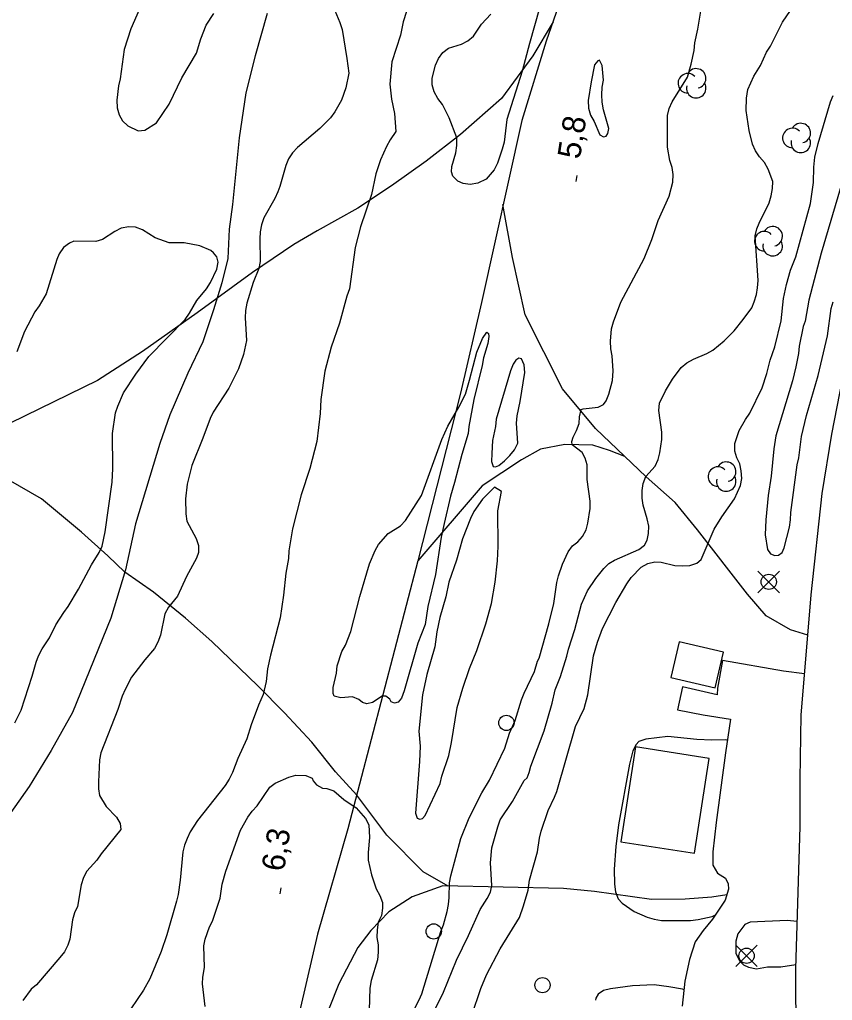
# Model space of a CAD drawing. Extents: x 282461 to 284471, y 5554090 to 5557646.
# Drawn here: x 282958.2 to 283064.7, y 5555423.2 to 5555551.7 of the extents above; entities that cross this region are included whole.
import ezdxf

# ---------------------------------------------------------------- set-up
doc = ezdxf.new("R2010")
doc.units = 0
for name, color, linetype in [('Niveau 1', 7, 'Continuous'), ('Niveau 19', 7, 'Continuous'), ('Niveau 2', 7, 'Continuous'), ('Niveau 21', 7, 'Continuous'), ('Niveau 22', 7, 'Continuous'), ('Niveau 3', 7, 'Continuous'), ('Niveau 31', 7, 'Continuous'), ('Niveau 36', 7, 'Continuous'), ('Niveau 44', 7, 'Continuous')]:
    doc.layers.add(name, color=color, linetype=linetype)

msp = doc.modelspace()

# ---------------------------------------------------------------- linework, layer by layer
at = {"layer": 'Niveau 1'}
for points in [[(283009.79, 5555555.65), (283008.45, 5555551.38), (283008.07, 5555549.65), (283006.95, 5555546.18), (283006.69, 5555543.24), (283006.88, 5555541.28), (283007.31, 5555539.38), (283007.45, 5555537.04)], [(283036.95, 5555514.69), (283040.01, 5555520.4), (283041.02, 5555522.9), (283041.85, 5555525.4), (283043.26, 5555528.55), (283043.76, 5555530.4), (283043.81, 5555531.39), (283043.68, 5555532.32), (283043.38, 5555533.24), (283043.07, 5555534.97), (283043.05, 5555539.11), (283043.28, 5555540.03), (283043.67, 5555540.9), (283045.66, 5555544.14), (283046.16, 5555545.87), (283046.55, 5555547.66), (283046.65, 5555548.64), (283047.04, 5555550.43), (283047.53, 5555553.31)], [(283007.45, 5555537.04), (283006.72, 5555535.93), (283006.26, 5555535.06), (283005.47, 5555533.31), (283004.86, 5555531.51), (283004.26, 5555528.78), (283002.86, 5555524.53), (283002.14, 5555521.86), (283001.4, 5555516.41), (283001.06, 5555515.48), (283000.07, 5555511.94), (282999.01, 5555508.8), (282998.18, 5555505.66), (282997.64, 5555501.95), (282997.55, 5555500.1), (282997.13, 5555496.44), (282996.19, 5555492.9), (282995.08, 5555489.47), (282993.92, 5555485), (282993.43, 5555482.1), (282993.39, 5555481.11), (282993.06, 5555479.2), (282992.75, 5555476.3), (282992.32, 5555473.34), (282991.05, 5555468.47), (282990.67, 5555466.67), (282990.46, 5555464.99), (282990.08, 5555463.3), (282989.46, 5555461.91), (282988.5, 5555459.35), (282987.95, 5555457.49), (282986.77, 5555454.93), (282986.09, 5555453.07), (282985.64, 5555452.2), (282985.13, 5555451.38), (282981.49, 5555446.82), (282980.52, 5555445.31), (282980.13, 5555444.43), (282979.79, 5555443.56), (282979.57, 5555442.69), (282979.21, 5555438.98), (282978.94, 5555437.13), (282978.72, 5555436.26), (282977.45, 5555431.84), (282976.72, 5555429.63), (282975.26, 5555426.09), (282974.41, 5555424.57), (282972.77, 5555422.12)], [(283009.22, 5555420.74), (283010.52, 5555423.3), (283010.86, 5555424.12), (283013.36, 5555432.25), (283013.7, 5555433.12), (283014.2, 5555434.87), (283014.36, 5555435.79), (283014.47, 5555436.72), (283014.5, 5555438.63), (283014.66, 5555439.56), (283015.99, 5555444.44), (283017.06, 5555447.17), (283018.75, 5555450.43), (283019.72, 5555452.07), (283021.75, 5555456.26), (283022.36, 5555458.23), (283023.09, 5555459.92), (283023.93, 5555462.59), (283024.27, 5555463.47), (283025.62, 5555466.32), (283026.01, 5555467.66), (283026.23, 5555468.06), (283027.51, 5555472.54), (283028.17, 5555475.21), (283028.54, 5555477.99), (283028.76, 5555478.86), (283029.32, 5555480.38), (283030.06, 5555482.01), (283030.63, 5555482.76), (283031.31, 5555483.29), (283031.94, 5555484), (283032.39, 5555484.87), (283032.62, 5555485.74), (283032.94, 5555487.66), (283032.93, 5555488.64), (283032.55, 5555491.47), (283032.52, 5555493.38), (283032.28, 5555494.25), (283031.87, 5555495), (283030.58, 5555496.02), (283030.52, 5555496.43), (283030.68, 5555497.01), (283031.14, 5555497.88), (283031.47, 5555498.81), (283031.52, 5555499.68), (283031.74, 5555500.61), (283032.03, 5555500.73), (283033.99, 5555500.93), (283034.68, 5555501.28), (283035.02, 5555501.75), (283035.36, 5555502.62), (283035.86, 5555504.42), (283035.96, 5555505.7), (283035.82, 5555507.67), (283035.64, 5555508.59), (283035.57, 5555509.58), (283035.72, 5555511.2), (283036, 5555512.13), (283036.95, 5555514.69)]]:
    msp.add_lwpolyline(points, dxfattribs=at)
at = {"layer": 'Niveau 19'}
for points in [[(283061.02, 5555466), (283058.27, 5555466.34), (283050.25, 5555467.76), (283049.6, 5555464.15), (283049.55, 5555463.28), (283045.02, 5555464.33), (283044.36, 5555461.31), (283047.73, 5555460.65), (283051.33, 5555460.06), (283050.64, 5555455.68), (283049.42, 5555446.55), (283049, 5555442.72), (283049.01, 5555440.97), (283049.59, 5555439.92), (283050.66, 5555439.27), (283051.02, 5555438.52), (283051.03, 5555437.82), (283050.63, 5555436.36), (283048.97, 5555433.9), (283047.72, 5555432.38), (283046.69, 5555430.92), (283045.92, 5555428.6), (283045.34, 5555425.77), (283044.99, 5555422.47)], [(283060.06, 5555433.58), (283058.74, 5555433.7), (283053.88, 5555433.47), (283053.18, 5555433.17), (283052.27, 5555431.94), (283051.99, 5555431.01), (283052.01, 5555429.44), (283052.49, 5555428.41), (283053.02, 5555427.89), (283053.66, 5555427.61), (283054.7, 5555427.39), (283056.15, 5555427.63), (283057.89, 5555427.65), (283059.88, 5555427.95)]]:
    msp.add_lwpolyline(points, dxfattribs=at)
at = {"layer": 'Niveau 2'}
for points in [[(283048.2, 5555507.95), (283049, 5555508.42), (283050.5, 5555509.6), (283051.81, 5555510.94), (283052.95, 5555512.41), (283054.09, 5555513.93), (283054.43, 5555514.74), (283054.71, 5555515.67), (283054.87, 5555516.54), (283054.92, 5555517.53), (283054.56, 5555523.38), (283054.78, 5555524.31), (283055.06, 5555525.01), (283056.36, 5555527.69), (283056.64, 5555528.62), (283056.8, 5555529.55), (283056.84, 5555530.48), (283056.25, 5555532.09), (283055.77, 5555532.96), (283055.13, 5555533.7), (283054.59, 5555534.51), (283054.18, 5555535.37), (283053.75, 5555537.17), (283053.37, 5555539.77), (283053.41, 5555541.39), (283053.57, 5555542.55), (283054.37, 5555544.28), (283055.23, 5555545.67), (283056.02, 5555547.41), (283056.53, 5555548.22), (283058.12, 5555551.35), (283060.79, 5555555.29)], [(282999.02, 5555553.94), (283000.15, 5555551.3), (283000.45, 5555550.38), (283001.06, 5555546.58), (283001.31, 5555544.68), (283000.93, 5555542.77), (283000.37, 5555541.15), (282999.46, 5555539.59), (282998.89, 5555538.83), (282997.52, 5555537.44), (282994.6, 5555534.94), (282993.91, 5555534.25), (282993.4, 5555533.44), (282993.06, 5555532.57), (282992.28, 5555529.83), (282992, 5555529.13), (282991.6, 5555528.26), (282990.19, 5555525.75), (282989.85, 5555524.82), (282989.69, 5555523.89), (282989.64, 5555522.96), (282989.68, 5555520), (282989.51, 5555519.08), (282988.78, 5555517.27), (282987.95, 5555514.54), (282987.79, 5555513.61), (282987.74, 5555512.62), (282987.89, 5555509.67), (282987.51, 5555507.81), (282986.84, 5555505.95), (282985.6, 5555503.44), (282983.55, 5555500.29), (282983.16, 5555499.47), (282982.2, 5555496.86), (282980.74, 5555493.3), (282980.13, 5555490.86), (282979.93, 5555488.95), (282979.95, 5555486.98), (282980.08, 5555486), (282981.32, 5555483.75), (282981.62, 5555482.83), (282981.63, 5555481.9), (282981.35, 5555481.14), (282980.05, 5555478.75), (282978.87, 5555476.19), (282977.67, 5555474.73), (282977.22, 5555473.85), (282976.62, 5555471.07), (282976.28, 5555470.14), (282975.83, 5555469.32), (282974.57, 5555467.86), (282972.86, 5555465.58), (282972.01, 5555463.95), (282971.62, 5555463.07), (282971.06, 5555461.33)], [(282973.84, 5555552.97), (282972.77, 5555550.48), (282971.87, 5555547.76), (282971.34, 5555543.95), (282971.12, 5555543.03), (282970.9, 5555541.13), (282970.97, 5555540.15), (282971.21, 5555539.22), (282971.68, 5555538.42), (282972.38, 5555537.79), (282973.72, 5555537.11), (282974.58, 5555537.23), (282976.13, 5555538.16), (282977.78, 5555540.6), (282979.42, 5555544.07), (282981.35, 5555547.31), (282981.91, 5555549.16), (282982.64, 5555550.95), (282983.61, 5555552.51)], [(283018.23, 5555530.28), (283017.2, 5555530.1), (283016.27, 5555530.21), (283015.58, 5555530.55), (283014.94, 5555531.18), (283014.76, 5555531.75), (283014.81, 5555532.44), (283015.31, 5555534.23), (283015.47, 5555535.21), (283015.46, 5555536.19), (283014.45, 5555538.83), (283013.57, 5555540.55), (283012.98, 5555541.35), (283012.51, 5555542.22), (283012.22, 5555543.13), (283012.21, 5555544), (283012.65, 5555545.73), (283013.05, 5555546.59), (283013.61, 5555547.4), (283014.36, 5555547.93), (283016.08, 5555548.46), (283016.89, 5555548.92), (283017.63, 5555549.5), (283018.71, 5555551.07), (283019.91, 5555552.4)], [(283026.31, 5555553.19), (283024.97, 5555548.58), (283024.03, 5555544.94), (283022.01, 5555538.59), (283021.64, 5555535.66), (283021.42, 5555534.73), (283020.8, 5555532.89), (283020.35, 5555532.02), (283019.32, 5555530.8), (283018.23, 5555530.28)], [(283033.04, 5555543.56), (283032.66, 5555541.08), (283032.73, 5555540.11), (283032.97, 5555539.19), (283033.44, 5555538.33), (283034.21, 5555536.6), (283034.67, 5555536.32), (283035.02, 5555536.44), (283035.25, 5555536.78), (283035.36, 5555537.42), (283034.69, 5555539.89), (283034.51, 5555540.87), (283034.44, 5555541.85), (283034.49, 5555542.82), (283034.66, 5555543.75), (283034.52, 5555545.7), (283034.17, 5555546.39), (283033.94, 5555546.28), (283033.48, 5555545.75), (283033.04, 5555543.56)], [(283017.43, 5555421.31), (283018.61, 5555424.8), (283019.34, 5555426.61), (283021.15, 5555429.99), (283023.65, 5555434.08), (283024.21, 5555435.65), (283024.82, 5555437.69), (283024.98, 5555438.97), (283026.04, 5555442.69), (283026.3, 5555444.49), (283026.52, 5555445.42), (283027.42, 5555448.1), (283028.27, 5555449.85), (283028.55, 5555450.61), (283030.99, 5555459.1), (283032.12, 5555461.49), (283032.62, 5555463.24), (283033.37, 5555468.35), (283033.87, 5555470.15), (283034.55, 5555471.96), (283036.3, 5555475.34), (283037.72, 5555477.8), (283038.29, 5555478.61), (283039.61, 5555479.96), (283040.47, 5555480.44), (283041.4, 5555480.68), (283042.21, 5555480.63), (283044.01, 5555480.19), (283045, 5555480.14), (283045.98, 5555480.21), (283046.9, 5555480.51), (283047.48, 5555480.98), (283049.17, 5555484.95), (283050.19, 5555486.58), (283051.85, 5555488.92), (283052.64, 5555490.67), (283052.8, 5555491.6), (283052.73, 5555492.59), (283052.54, 5555493.51), (283052.13, 5555494.32), (283051.89, 5555495.19), (283051.87, 5555496.17), (283052.43, 5555497.86), (283053.28, 5555499.32), (283053.85, 5555500.14), (283055.44, 5555503.47), (283056.05, 5555505.33), (283056.49, 5555507.07), (283057.11, 5555508.82), (283057.94, 5555512.25), (283058.25, 5555515.16), (283058.63, 5555517.02), (283059.19, 5555518.88), (283059.87, 5555520.63), (283061.81, 5555527.61), (283062.18, 5555530.34), (283062.22, 5555532.38), (283062.34, 5555533.69), (283062.79, 5555535.48), (283064.41, 5555540.92), (283064.75, 5555541.73)], [(283066.85, 5555533.51), (283063.17, 5555521.1), (283061.57, 5555514.93), (283061.08, 5555512.19), (283060.85, 5555511.5), (283060.3, 5555508.93), (283060.2, 5555507.95), (283059.87, 5555506.2), (283059.43, 5555504.4), (283057.26, 5555497.17), (283056.99, 5555495.49), (283056.62, 5555491.88), (283056.25, 5555489.38)], [(282981.78, 5555522.06), (282979.75, 5555522.44), (282977.78, 5555522.47), (282975.92, 5555523.09), (282974.28, 5555524.17), (282973.35, 5555524.51), (282972.49, 5555524.55), (282971.5, 5555524.37), (282970.64, 5555523.95), (282969.03, 5555522.89), (282968.17, 5555522.65), (282965.27, 5555522.67), (282964.7, 5555522.43), (282963.95, 5555521.84), (282963.38, 5555521.03), (282963.05, 5555520.27), (282961.65, 5555515.79), (282960.75, 5555514.22), (282960.18, 5555513.4), (282958.82, 5555510.83), (282957.81, 5555508.16)], [(282957.54, 5555459.61), (282958.39, 5555461.24), (282959.84, 5555465.72), (282960.34, 5555467.52), (282960.67, 5555468.39), (282961.13, 5555469.27), (282962.09, 5555470.72), (282962.94, 5555472.41), (282963.96, 5555474.05), (282964.53, 5555474.81), (282965.89, 5555477.08), (282967.59, 5555480.29), (282968.61, 5555481.92), (282969.01, 5555482.74), (282969.39, 5555484.6), (282970.29, 5555491.1), (282970.39, 5555492.89), (282970.33, 5555497.47), (282970.76, 5555500.2), (282971.04, 5555501.07), (282971.77, 5555502.82), (282973.42, 5555505.27), (282975.13, 5555507.55), (282979.87, 5555512.41), (282980.44, 5555513.23), (282981.4, 5555514.92), (282982.66, 5555516.45), (282983.17, 5555517.26), (282984.02, 5555519.01), (282984.18, 5555519.94), (282984, 5555520.63), (282983.58, 5555521.15), (282983.23, 5555521.44), (282981.78, 5555522.06)], [(283056.25, 5555489.38), (283055.94, 5555486.19), (283055.85, 5555484.21), (283056.16, 5555482.3), (283056.57, 5555481.72), (283057.1, 5555481.5), (283057.62, 5555481.56), (283058.08, 5555481.91), (283058.36, 5555482.5), (283059.03, 5555485.23), (283059.19, 5555486.17), (283059.23, 5555487.15), (283060.03, 5555493.37), (283060.25, 5555494.3), (283060.62, 5555497.1), (283061.28, 5555499.83), (283062.79, 5555505.07), (283064, 5555510.26), (283064.48, 5555513.86), (283064.76, 5555514.73)], [(283011.29, 5555472.48), (283010.33, 5555470.03), (283008.56, 5555463.77), (283008.23, 5555462.84), (283007.77, 5555462.31), (283007.31, 5555462.19), (283006.84, 5555462.36), (283006.67, 5555462.7), (283006.14, 5555463.1), (283005.68, 5555463.1), (283004.42, 5555462.27), (283003.67, 5555462.09), (283003.09, 5555462.26), (283002.62, 5555462.66), (283001.81, 5555462.99), (283000.25, 5555462.86), (282999.38, 5555463.08), (282999.26, 5555463.43), (282999.25, 5555464.24), (282999.69, 5555466.09), (282999.79, 5555467.08), (283000.4, 5555468.94), (283000.86, 5555469.75), (283001.59, 5555471.55), (283002.74, 5555476.14), (283004.02, 5555480.43), (283004.75, 5555482.18), (283005.2, 5555482.93), (283006.46, 5555484.39), (283008.06, 5555485.4), (283008.75, 5555486.1), (283010.85, 5555489.36), (283013.48, 5555496.68), (283014.26, 5555498.43), (283015.74, 5555500.93), (283016.58, 5555502.62), (283017.14, 5555504.48), (283018.08, 5555508.14), (283018.81, 5555509.94), (283019.38, 5555510.76), (283019.61, 5555510.58), (283019.67, 5555510.18), (283019.51, 5555509.25), (283018.95, 5555507.39), (283018.79, 5555506.41), (283017.69, 5555501.94), (283017.04, 5555498.4), (283016.94, 5555497.48), (283016.1, 5555494.75), (283015.16, 5555491.09), (283014.61, 5555489.29), (283013.78, 5555485.7), (283013.4, 5555483.9), (283012.65, 5555479.03), (283011.66, 5555474.85), (283011.29, 5555472.48)], [(283011.63, 5555420.08), (283013.72, 5555424.33), (283015.4, 5555428.52), (283016.99, 5555431.73), (283018.51, 5555435.16), (283019.42, 5555436.57), (283019.87, 5555437.44), (283020.03, 5555438.31), (283019.88, 5555441.26), (283020.03, 5555443.24), (283020.81, 5555445.97), (283021.14, 5555446.9), (283022.74, 5555449.29), (283024.27, 5555452.03), (283024.67, 5555452.39), (283024.95, 5555453.08), (283025.17, 5555453.9), (283026.91, 5555458.55), (283027.96, 5555462.16), (283028.35, 5555463.9), (283029.02, 5555465.65), (283029.86, 5555468.32), (283030.08, 5555469.25), (283030.92, 5555471.81), (283031.8, 5555475.13), (283032.59, 5555476.87), (283033.67, 5555478.51), (283034.7, 5555479.8), (283035.39, 5555480.44), (283036.13, 5555480.91), (283039.3, 5555482.28), (283040.05, 5555482.87), (283040.39, 5555483.51), (283040.55, 5555484.38), (283040.6, 5555485.37), (283040.41, 5555486.29), (283039.87, 5555488.08), (283039.74, 5555489.01), (283039.73, 5555490), (283039.89, 5555490.92), (283040.23, 5555491.86), (283041.43, 5555493.2), (283041.82, 5555494.08), (283042.04, 5555494.95), (283042.31, 5555496.69), (283042.3, 5555497.68), (283041.92, 5555500.51), (283042.02, 5555501.44), (283042.81, 5555503.07), (283043.72, 5555504.59), (283044.86, 5555506.11), (283045.61, 5555506.76), (283046.47, 5555507.23), (283048.2, 5555507.95)], [(283020.03, 5555494.85), (283019.99, 5555493.81), (283020.23, 5555493.18), (283020.52, 5555493.12), (283020.98, 5555493.3), (283021.72, 5555493.89), (283022.41, 5555494.59), (283023.03, 5555495.35), (283023.43, 5555496.22), (283023.28, 5555498.82), (283023.38, 5555499.81), (283023.77, 5555501.66), (283024.35, 5555505.49), (283024.28, 5555506.47), (283023.93, 5555507.28), (283023.58, 5555507.33), (283023.18, 5555507.1), (283022.84, 5555506.57), (283022.5, 5555505.7), (283020.61, 5555499.37), (283020.51, 5555498.39), (283020.13, 5555496.59), (283020.03, 5555494.85)], [(283010.67, 5555456.56), (283010.58, 5555454.53), (283010.03, 5555447.76), (283010.27, 5555447.13), (283010.62, 5555446.96), (283010.96, 5555447.08), (283011.3, 5555447.48), (283013.28, 5555451.67), (283013.5, 5555452.6), (283014.39, 5555455.33), (283014.77, 5555457.01), (283015.52, 5555461.59), (283016.25, 5555464.14), (283017.14, 5555466.7), (283018.09, 5555469.08), (283019.26, 5555472.57), (283019.98, 5555475.24), (283020.47, 5555478.02), (283020.78, 5555480.8), (283020.87, 5555482.71), (283020.82, 5555487.34), (283021.31, 5555489.89), (283020.38, 5555490.46), (283018.83, 5555488.88), (283017.7, 5555487.25), (283017.25, 5555486.37), (283016.18, 5555483.7), (283015.4, 5555480.91), (283014.4, 5555478.01), (283014.02, 5555476.09), (283013.24, 5555473.37), (283012.86, 5555471.51), (283012.59, 5555469.54), (283011.54, 5555465.94), (283010.94, 5555463.27), (283010.47, 5555458.52), (283010.67, 5555456.56)], [(282971.06, 5555461.33), (282968.82, 5555455.68), (282968.65, 5555454.75), (282968.52, 5555451.86), (282968.53, 5555450.93), (282968.65, 5555450.06), (282969.54, 5555448.62), (282970.89, 5555447.25), (282971.36, 5555446.39), (282971.43, 5555445.63), (282968.86, 5555442.42), (282968.3, 5555441.6), (282966.98, 5555440.19), (282966.53, 5555439.32), (282966.25, 5555438.39), (282965.77, 5555435.55), (282965.37, 5555434.73), (282965.09, 5555433.8), (282964.78, 5555431.25), (282964.5, 5555430.49), (282964.04, 5555429.62), (282963.47, 5555428.86), (282960.39, 5555425.29), (282959.71, 5555424.7), (282958.62, 5555423.24)], [(283051.01, 5555457.31), (283050.72, 5555457.36), (283048.87, 5555457.34), (283046.9, 5555457.43), (283043.12, 5555457.79), (283040.23, 5555457.47), (283039.31, 5555457.17), (283038.96, 5555456.76), (283038.51, 5555455.94), (283038.07, 5555454.2), (283036.66, 5555446.23), (283036.29, 5555443.39), (283036.09, 5555440.43), (283036.11, 5555438.46), (283036.24, 5555437.47), (283036.6, 5555436.55), (283037.13, 5555435.98), (283038.71, 5555434.89), (283040.4, 5555434.16), (283041.33, 5555433.88), (283042.26, 5555433.71), (283046.08, 5555433.7), (283047.07, 5555433.83), (283048.92, 5555434.25), (283049.33, 5555434.43)], [(282982.48, 5555422.46), (282982.15, 5555425.4), (282982.2, 5555426.27), (282982.42, 5555427.55), (282982.32, 5555430.38), (282982.49, 5555431.25), (282983.04, 5555432.87), (282983.44, 5555433.63), (282983.72, 5555434.39), (282984.44, 5555436.65), (282984.71, 5555438.45), (282985.21, 5555440.19), (282987.11, 5555445.53), (282988.07, 5555447.22), (282988.64, 5555448.03), (282989.32, 5555448.74), (282990.97, 5555451.18), (282991.66, 5555451.71), (282993.44, 5555452.49), (282994.36, 5555452.73), (282995.69, 5555452.68), (282996.5, 5555452.35), (282996.62, 5555452), (282997.09, 5555451.49), (282997.85, 5555451.03), (282998.43, 5555450.98), (282999.36, 5555450.7), (283000.64, 5555449.56), (283002.27, 5555448.48), (283003.5, 5555447.05), (283003.92, 5555446.24), (283004, 5555444.57), (283003.85, 5555442.6), (283003.86, 5555441.61), (283004.29, 5555439.71), (283004.89, 5555437.87), (283005.36, 5555437), (283005.72, 5555436.08), (283005.73, 5555435.33), (283005.57, 5555434.35), (283005.17, 5555433.47), (283005.01, 5555432.49), (283004.97, 5555431.5), (283005.15, 5555430.52), (283005.16, 5555429.54), (283005.06, 5555428.56), (283004.23, 5555425.83), (283004.07, 5555424.84), (283003.99, 5555421.95)], [(283045.22, 5555424.64), (283045.03, 5555424.7), (283043.23, 5555425.03), (283041.32, 5555425.29), (283038.48, 5555425.15), (283035.59, 5555424.77), (283034.66, 5555424.52), (283033.97, 5555424.05), (283033.69, 5555423.53), (283033.61, 5555423.28)]]:
    msp.add_lwpolyline(points, dxfattribs=at)
at = {"layer": 'Niveau 21'}
msp.add_lwpolyline([(283059.96, 5555174.63), (283060.09, 5555177.87), (283060.21, 5555186.07), (283060.12, 5555201.45), (283060.36, 5555210.73), (283060.14, 5555228.29), (283060.53, 5555244.18), (283060.56, 5555263.98), (283060.77, 5555271.18), (283060.27, 5555303.27), (283060.09, 5555324.29), (283060.11, 5555345.02), (283059.8, 5555365.9), (283059.95, 5555377.73), (283060.17, 5555387.77), (283059.98, 5555399.2), (283059.86, 5555427.39), (283060.45, 5555446.02), (283060.43, 5555452.22), (283060.56, 5555460.58), (283061.88, 5555476.37), (283063.34, 5555489.62), (283064.58, 5555497.41), (283066.66, 5555507.93)], dxfattribs=at)
at = {"layer": 'Niveau 22'}
for points in [[(283047.36, 5555617.16), (283046.17, 5555609.2), (283044.22, 5555598.8), (283042.3, 5555589.49), (283038.61, 5555578.39), (283035.11, 5555570.19), (283031.4, 5555561.06), (283027.17, 5555548.85), (283023.97, 5555538.49), (283018.68, 5555514.63), (283015.92, 5555502.75), (283010.33, 5555480.8), (283001.17, 5555445.7), (282997.2, 5555431.92), (282994.29, 5555419.31)], [(282990.61, 5555552.51), (282989.05, 5555546.96), (282987.83, 5555542.11), (282986.96, 5555536.22), (282986.06, 5555527.48), (282985.63, 5555524.24), (282985.45, 5555520.42), (282984.68, 5555517.22), (282983.6, 5555513.67), (282982.18, 5555509.48), (282980.24, 5555505.39), (282977.85, 5555499.91), (282976.56, 5555496.18), (282973.36, 5555485.66), (282972.04, 5555479.62), (282970.15, 5555473.28), (282965.09, 5555460.94), (282962.32, 5555455.98), (282959.42, 5555451.26), (282955.67, 5555445.94), (282951.35, 5555439.17), (282947.78, 5555432.64), (282945.47, 5555425.59), (282943.64, 5555419.4)], [(283028.06, 5555551.41), (283025.42, 5555546.96), (283021.32, 5555541.36), (283015.94, 5555536.66), (283011.44, 5555533.13), (283006.88, 5555529.94), (283002.48, 5555526.99), (282997.15, 5555524.02), (282994.12, 5555522.24), (282988.68, 5555518.57), (282981.44, 5555513.27), (282974.26, 5555508.21), (282968.4, 5555504.44), (282949.29, 5555495.12)], [(283061.44, 5555471.07), (283059.18, 5555471.79), (283056, 5555473.59), (283053.52, 5555476.46), (283046.99, 5555484.89), (283044.08, 5555488.47), (283040.28, 5555491.81), (283033.62, 5555498.16), (283029.31, 5555503.34), (283024.41, 5555513.03), (283022.74, 5555520.54), (283021.49, 5555527.48)], [(283037.47, 5555494.49), (283035.46, 5555495.27), (283033.28, 5555495.95), (283029.61, 5555496.04), (283026.42, 5555495.43), (283023.92, 5555494.03), (283018.8, 5555490.63), (283010.33, 5555480.8)], [(283014.31, 5555438.22), (283011.06, 5555440.06), (283006.3, 5555444.89), (283002.35, 5555450.13), (282999.55, 5555453.18), (282996.46, 5555457.05), (282992.9, 5555460.92), (282989.41, 5555464.43), (282983.35, 5555470.23), (282979.91, 5555473.3), (282975.72, 5555476.69), (282971.95, 5555479.32), (282969.73, 5555481.48), (282966.27, 5555484.58), (282961.06, 5555488.94), (282955.23, 5555492.23)], [(283050.83, 5555437.09), (283048.86, 5555436.78), (283045.39, 5555436.51), (283040.98, 5555436.46), (283033.51, 5555437.5), (283029.45, 5555437.92), (283013.61, 5555438.23), (283009.62, 5555436.82), (283006.56, 5555434.84), (283004.21, 5555432.41), (283002.5, 5555430.19), (283000.01, 5555425.42), (282997.55, 5555419.27), (282996.51, 5555415.41), (282994.94, 5555411.46), (282992.38, 5555403.33)]]:
    msp.add_lwpolyline(points, dxfattribs=at)
at = {"layer": 'Niveau 3'}
for p, q in [((283031.1, 5555530.48), (283031.22, 5555531.27)), ((282992.33, 5555437.19), (282992.45, 5555437.98))]:
    msp.add_line(p, q, dxfattribs=at)
at = {"layer": 'Niveau 31'}
for points in [[(283043.49, 5555465.54), (283049.3, 5555464.19), (283050.39, 5555468.85), (283044.58, 5555470.2), (283043.49, 5555465.54)], [(283048.51, 5555454.94), (283038.88, 5555456.43), (283036.95, 5555444.01), (283046.58, 5555442.52), (283048.51, 5555454.94)]]:
    msp.add_lwpolyline(points, dxfattribs=at)
at = {"layer": 'Niveau 36'}
for p, q in [((283057.73, 5555476.64), (283054.91, 5555479.46)), ((283054.91, 5555476.64), (283057.73, 5555479.46)), ((283054.82, 5555427.67), (283052, 5555430.49)), ((283052, 5555427.67), (283054.82, 5555430.49))]:
    msp.add_line(p, q, dxfattribs=at)
for centre in [(283056.33, 5555478.06), (283021.95, 5555459.59), (283012.43, 5555432.28), (283053.42, 5555429.09), (283026.68, 5555425.24)]:
    msp.add_circle(centre, 1, dxfattribs=at)
at = {"layer": 'Niveau 44'}
for centre, start, end in [((283046.82, 5555543.99), 282.2692, 149.7263), ((283045.72, 5555543.35), 44.1154, 269.804), ((283046.82, 5555542.71), 166.9369, 29.6212), ((283059.42, 5555536.19), 44.1154, 269.804), ((283060.52, 5555536.83), 282.2692, 149.7263), ((283060.52, 5555535.55), 166.9369, 29.6212), ((283056.84, 5555523.31), 282.2692, 149.7263), ((283055.74, 5555522.67), 44.1154, 269.804), ((283056.84, 5555522.03), 166.9369, 29.6212), ((283050.75, 5555492.48), 282.2692, 149.7263), ((283049.66, 5555491.84), 44.1154, 269.804), ((283050.75, 5555491.2), 166.9369, 29.6212)]:
    msp.add_arc(centre, 1.28, start, end, dxfattribs=at)

# ---------------------------------------------------------------- texts
at = {"layer": 'Niveau 3'}
for s, p in [('5,8  ', (283031.58, 5555533.32)), ('6,3  ', (282992.81, 5555440.03))]:
    msp.add_text(s, height=3, rotation=81.0957, dxfattribs=at).set_placement(p)

doc.saveas('drawing.dxf')
